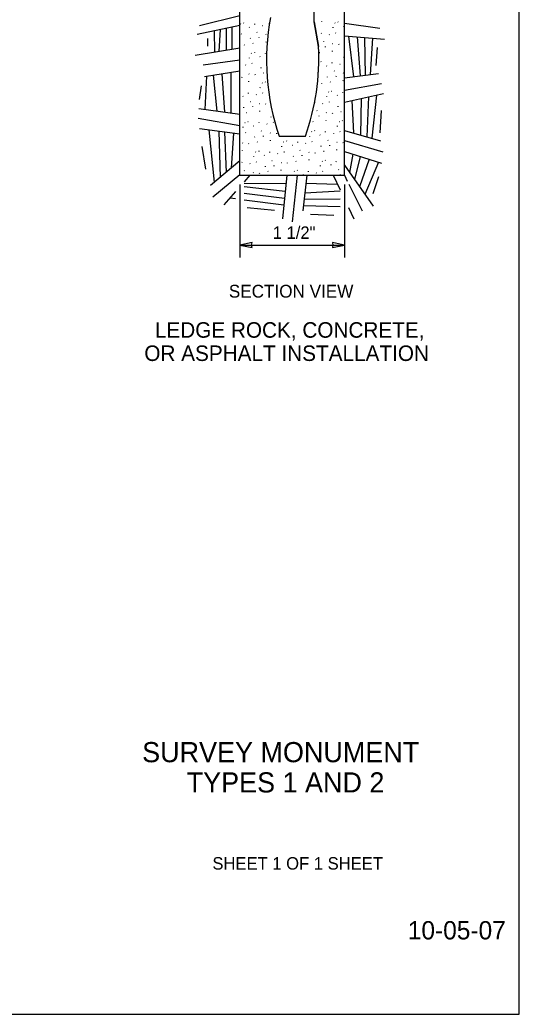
# Model space of a CAD drawing. Extents: x 99862 to 103151, y 100000 to 102076.
# Drawn here: x 102507 to 103151, y 100000 to 101282 of the extents above; entities that cross this region are included whole.
import ezdxf

# ---------------------------------------------------------------- set-up
doc = ezdxf.new("R2010")
doc.units = 0
for name, color, linetype in [('Level 1', 7, 'Continuous'), ('Level 11', 7, 'Continuous'), ('Level 15', 7, 'Continuous'), ('Level 20', 7, 'Continuous'), ('Level 21', 7, 'Continuous'), ('Level 26', 7, 'Continuous'), ('Level 28', 7, 'Continuous'), ('Level 6', 7, 'Continuous'), ('Level 62', 7, 'Continuous')]:
    doc.layers.add(name, color=color, linetype=linetype)

msp = doc.modelspace()

# ---------------------------------------------------------------- linework, layer by layer
at = {"layer": 'Level 1'}
msp.add_lwpolyline([(99862, 99999.5), (103151, 99999.5), (103151, 102075.5), (99862, 102075.5)], close=True, dxfattribs=at)
at = {"layer": 'Level 11'}
for p, q in [((102790.8, 101081.2), (102790.8, 101368.8)), ((102925.8, 101081.2), (102925.8, 101368.8)), ((102790.8, 101081.2), (102925.8, 101081.2))]:
    msp.add_line(p, q, dxfattribs=at)
at = {"layer": 'Level 15'}
for p, q in [((102790.8, 101069.2), (102790.8, 100975.2)), ((102925.8, 101069.2), (102925.8, 100975.2)), ((102790.8, 100991.2), (102925.8, 100991.2))]:
    msp.add_line(p, q, dxfattribs=at)
for points in [[(102790.8, 100991.2), (102806.5, 100988.1), (102805.8, 100991.2), (102806.5, 100994.3)], [(102925.8, 100991.2), (102910.1, 100994.3), (102910.8, 100991.2), (102910.1, 100988.1)]]:
    msp.add_lwpolyline(points, close=True, dxfattribs=at)
at = {"layer": 'Level 26'}
for p, q in [((102791.7, 101276.5), (102792.1, 101276.2)), ((102795.6, 101277.8), (102796, 101277.4)), ((102802.8, 101272.2), (102803.2, 101271.9)), ((102810.1, 101275.7), (102810.1, 101276.5)), ((102820.1, 101274.5), (102820.5, 101274.2)), ((102828.3, 101276.7), (102828.8, 101276.4)), ((102896.5, 101278.9), (102896.6, 101279.6)), ((102911.3, 101271.3), (102911.3, 101272)), ((102913.4, 101277.7), (102913.8, 101277.4)), ((102917.3, 101279), (102917.8, 101278.7)), ((102924.5, 101273.4), (102924.9, 101273.1)), ((102792.4, 101263.6), (102792.8, 101263.3)), ((102804.3, 101257.4), (102804.4, 101258.1)), ((102812.7, 101265.6), (102813.2, 101265.3)), ((102815.6, 101258.3), (102815.7, 101259)), ((102824.5, 101263.1), (102824.9, 101262.8)), ((102895.8, 101263.9), (102895.9, 101264.6)), ((102905.8, 101262.6), (102906.3, 101262.3)), ((102914.1, 101264.8), (102914.5, 101264.5)), ((102796.4, 101249.4), (102796.6, 101248.8)), ((102807.6, 101251.5), (102808, 101251.2)), ((102824.6, 101252.7), (102824.7, 101253.4)), ((102898.5, 101253.7), (102898.9, 101253.4)), ((102901.4, 101246.5), (102901.4, 101247.2)), ((102910.3, 101251.2), (102910.7, 101250.9)), ((102918.1, 101250.6), (102918.4, 101250)), ((102803.4, 101232), (102803.4, 101232.7)), ((102805.6, 101238.5), (102806, 101238.2)), ((102809.5, 101239.7), (102809.9, 101239.4)), ((102816.6, 101234.2), (102817, 101233.9)), ((102823.9, 101237.7), (102823.9, 101238.4)), ((102893.4, 101239.6), (102893.8, 101239.3)), ((102910.4, 101240.9), (102910.4, 101241.6)), ((102925.1, 101233.2), (102925.2, 101234)), ((102798, 101223.4), (102798.4, 101223.1)), ((102806.2, 101225.6), (102806.6, 101225.2)), ((102818.2, 101219.3), (102818.2, 101220)), ((102895.2, 101227.9), (102895.6, 101227.6)), ((102902.4, 101222.3), (102902.8, 101222)), ((102909.7, 101225.9), (102909.7, 101226.6)), ((102919.7, 101224.6), (102920.1, 101224.3)), ((102790.8, 101214.3), (102791, 101214.1)), ((102793.5, 101207.2), (102793.6, 101207.9)), ((102802.4, 101211.9), (102802.8, 101211.6)), ((102810.2, 101211.4), (102810.5, 101210.8)), ((102821.5, 101213.4), (102821.9, 101213.1)), ((102892, 101213.7), (102892.4, 101213.4)), ((102903.9, 101207.5), (102904, 101208.2)), ((102912.3, 101215.7), (102912.8, 101215.4)), ((102915.2, 101208.4), (102915.3, 101209.2)), ((102924.1, 101213.2), (102924.5, 101212.9)), ((102924.2, 101202.8), (102924.3, 101203.6)), ((102802.5, 101201.6), (102802.6, 101202.3)), ((102817.2, 101194), (102817.3, 101194.7)), ((102819.4, 101200.4), (102819.8, 101200.1)), ((102823.3, 101201.7), (102823.7, 101201.4)), ((102896, 101199.5), (102896.2, 101198.9)), ((102907.2, 101201.6), (102907.6, 101201.3)), ((102794.5, 101183.1), (102794.9, 101182.7)), ((102801.8, 101186.6), (102801.8, 101187.3)), ((102811.8, 101185.3), (102812.2, 101185)), ((102820.1, 101187.5), (102820.5, 101187.2)), ((102903, 101182.1), (102903, 101182.8)), ((102905.2, 101188.6), (102905.6, 101188.3)), ((102909.1, 101189.8), (102909.5, 101189.5)), ((102916.2, 101184.3), (102916.6, 101184)), ((102923.5, 101187.8), (102923.5, 101188.5)), ((102796.1, 101168.2), (102796.1, 101168.9)), ((102804.5, 101176.4), (102804.9, 101176.1)), ((102807.4, 101169.2), (102807.4, 101169.9)), ((102816.3, 101173.9), (102816.7, 101173.6)), ((102824, 101173.3), (102824.3, 101172.8)), ((102887.5, 101174.7), (102887.6, 101175.5)), ((102897.6, 101173.5), (102898, 101173.2)), ((102905.8, 101175.7), (102906.2, 101175.4)), ((102917.8, 101169.4), (102917.8, 101170.2)), ((102799.3, 101162.3), (102799.8, 101162)), ((102816.4, 101163.6), (102816.4, 101164.3)), ((102831.1, 101156), (102831.1, 101156.7)), ((102890.2, 101164.6), (102890.6, 101164.3)), ((102893.1, 101157.3), (102893.2, 101158)), ((102902, 101162.1), (102902.4, 101161.7)), ((102902.1, 101151.7), (102902.2, 101152.4)), ((102909.8, 101161.5), (102910.1, 101160.9)), ((102921, 101163.5), (102921.5, 101163.2)), ((102795.1, 101142.9), (102795.2, 101143.6)), ((102797.3, 101149.3), (102797.7, 101149)), ((102801.2, 101150.6), (102801.6, 101150.3)), ((102808.3, 101145), (102808.8, 101144.7)), ((102815.6, 101148.6), (102815.7, 101149.3)), ((102825.6, 101147.3), (102826.1, 101147)), ((102833.9, 101149.5), (102834.3, 101149.2)), ((102885.1, 101150.5), (102885.5, 101150.2)), ((102916.8, 101144.1), (102916.9, 101144.8)), ((102919, 101150.6), (102919.4, 101150.3)), ((102922.9, 101151.8), (102923.3, 101151.5)), ((102797.9, 101136.4), (102798.4, 101136.1)), ((102809.9, 101130.2), (102810, 101130.9)), ((102818.3, 101138.4), (102818.7, 101138.1)), ((102821.2, 101131.2), (102821.2, 101131.9)), ((102830.1, 101135.9), (102830.5, 101135.6)), ((102837.9, 101135.3), (102838.2, 101134.7)), ((102880.9, 101131), (102880.9, 101131.7)), ((102883, 101137.5), (102883.5, 101137.2)), ((102886.9, 101138.7), (102887.4, 101138.4)), ((102894.1, 101133.2), (102894.5, 101132.9)), ((102901.4, 101136.7), (102901.4, 101137.4)), ((102911.4, 101135.5), (102911.8, 101135.2)), ((102919.7, 101137.6), (102920.1, 101137.3)), ((102794.1, 101122.8), (102794.6, 101122.5)), ((102801.9, 101122.2), (102802.2, 101121.6)), ((102813.2, 101124.3), (102813.6, 101124)), ((102830.2, 101125.6), (102830.3, 101126.3)), ((102844.9, 101117.9), (102845, 101118.6)), ((102847.1, 101124.4), (102847.5, 101124.1)), ((102851, 101125.6), (102851.4, 101125.3)), ((102858.1, 101120.1), (102858.6, 101119.8)), ((102865.4, 101123.6), (102865.5, 101124.3)), ((102875.4, 101122.4), (102875.9, 101122.1)), ((102883.7, 101124.6), (102884.1, 101124.2)), ((102895.7, 101118.3), (102895.7, 101119)), ((102904.1, 101126.5), (102904.5, 101126.2)), ((102907, 101119.3), (102907, 101120)), ((102915.9, 101124), (102916.3, 101123.7)), ((102916, 101113.7), (102916, 101114.4)), ((102923.6, 101123.5), (102923.9, 101122.9)), ((102794.2, 101112.5), (102794.3, 101113.2)), ((102809, 101104.8), (102809, 101105.5)), ((102811.1, 101111.3), (102811.5, 101111)), ((102815, 101112.5), (102815.5, 101112.2)), ((102822.2, 101107), (102822.6, 101106.7)), ((102829.5, 101110.5), (102829.5, 101111.2)), ((102839.5, 101109.3), (102839.9, 101109)), ((102847.7, 101111.5), (102848.2, 101111.2)), ((102859.7, 101105.2), (102859.8, 101106)), ((102868.1, 101113.4), (102868.5, 101113.1)), ((102871, 101106.2), (102871, 101106.9)), ((102879.9, 101110.9), (102880.3, 101110.6)), ((102880, 101100.6), (102880.1, 101101.3)), ((102887.7, 101110.4), (102888, 101109.8)), ((102898.9, 101112.4), (102899.4, 101112.1)), ((102793.5, 101097.5), (102793.6, 101098.2)), ((102803.5, 101096.2), (102804, 101095.9)), ((102811.8, 101098.4), (102812.2, 101098.1)), ((102823.8, 101092.2), (102823.8, 101092.9)), ((102832.2, 101100.4), (102832.6, 101100)), ((102835, 101093.1), (102835.1, 101093.8)), ((102843.9, 101097.8), (102844.4, 101097.5)), ((102844, 101087.5), (102844.1, 101088.2)), ((102851.7, 101097.3), (102852, 101096.7)), ((102863, 101099.3), (102863.4, 101099)), ((102894.7, 101093), (102894.8, 101093.7)), ((102896.9, 101099.4), (102897.3, 101099.1)), ((102900.8, 101100.7), (102901.2, 101100.4)), ((102907.9, 101095.1), (102908.4, 101094.8)), ((102915.2, 101098.7), (102915.3, 101099.4)), ((102917.9, 101088.5), (102918.3, 101088.2)), ((102925.2, 101097.4), (102925.7, 101097.1)), ((102796.2, 101087.3), (102796.6, 101087)), ((102808, 101084.8), (102808.4, 101084.5)), ((102815.8, 101084.2), (102816.1, 101083.6)), ((102827, 101086.3), (102827.4, 101085.9)), ((102860.9, 101086.4), (102861.3, 101086)), ((102864.8, 101087.6), (102865.3, 101087.3)), ((102872, 101082.1), (102872.4, 101081.7)), ((102879.3, 101085.6), (102879.3, 101086.3)), ((102889.3, 101084.3), (102889.7, 101084)), ((102897.5, 101086.5), (102898, 101086.2)), ((102920.8, 101081.3), (102920.8, 101082))]:
    msp.add_line(p, q, dxfattribs=at)
at = {"layer": 'Level 28'}
for p, q in [((102790.8, 101286.7), (102738.8, 101273.9)), ((102790.8, 101274.4), (102735.6, 101262.9)), ((102765.3, 101269.1), (102763.8, 101240.6)), ((102773.3, 101270.8), (102773.3, 101242.1)), ((102780.3, 101272.2), (102780.3, 101243.3)), ((102925.8, 101277.3), (102971.2, 101270.8)), ((102748.9, 101257.5), (102748.9, 101247.8)), ((102757.6, 101267.5), (102758.3, 101239.7)), ((102925.8, 101261.1), (102977.4, 101256.7)), ((102930.9, 101260.7), (102937.3, 101208.1)), ((102942.3, 101259.7), (102946.1, 101209.2)), ((102951.7, 101258.9), (102952.5, 101210)), ((102962, 101258), (102959, 101210.9)), ((102790.8, 101245), (102733.3, 101235.6)), ((102967.7, 101246.1), (102966.4, 101222.7)), ((102790.8, 101229.7), (102743.4, 101223.2)), ((102790.8, 101215.4), (102745, 101208.3)), ((102747.7, 101208.8), (102745.5, 101165.9)), ((102756.2, 101210.1), (102761.3, 101163.7)), ((102767.5, 101211.8), (102771.1, 101162.4)), ((102779.4, 101161.2), (102779.4, 101213.6)), ((102925.8, 101206.6), (102969.6, 101212.2)), ((102741, 101196.7), (102738.3, 101179)), ((102925.8, 101191.1), (102973.5, 101199.7)), ((102925.8, 101175.6), (102975.9, 101186.5)), ((102947.2, 101180.2), (102946.5, 101133)), ((102956.8, 101182.3), (102954.7, 101130.6)), ((102967, 101184.5), (102961, 101128.8)), ((102790.8, 101159.6), (102738, 101167)), ((102935.2, 101177.6), (102937.3, 101135.7)), ((102790.8, 101144.8), (102737.2, 101154.5)), ((102973, 101164.9), (102971.2, 101135.8)), ((102790.8, 101134.3), (102738.8, 101141.2)), ((102750.7, 101139.6), (102757.8, 101072.1)), ((102763.7, 101137.9), (102765.2, 101078.2)), ((102770.9, 101137), (102773, 101084.8)), ((102782.7, 101135.4), (102779.7, 101090.3)), ((102925.8, 101139), (102972, 101125.6)), ((102741.9, 101118.1), (102746.3, 101089)), ((102925.8, 101126.1), (102975.1, 101111.6)), ((102925.8, 101111.7), (102973.5, 101096.8)), ((102936.4, 101108.4), (102932.4, 101084.7)), ((102946, 101105.4), (102938.7, 101075.6)), ((102957.5, 101101.8), (102945.2, 101066.4)), ((102790.8, 101099.6), (102752.8, 101067.9)), ((102925.8, 101094.1), (102962.6, 101041.4)), ((102969.7, 101098), (102952.2, 101056.3)), ((102790.8, 101081.7), (102755.9, 101053.1)), ((102803.7, 101081.2), (102796.3, 101072.8)), ((102851.4, 101081.2), (102845.6, 101025)), ((102864.9, 101081.2), (102858.1, 101021.1)), ((102877.2, 101081.2), (102872.1, 101035.1)), ((102911.3, 101081.2), (102920.2, 101062.2)), ((102925.6, 101081.2), (102929.3, 101073.6)), ((102969.5, 101079.3), (102962.4, 101057.2)), ((102796.3, 101071.1), (102850.3, 101070.4)), ((102796.3, 101066.6), (102849.3, 101060.6)), ((102876.1, 101071.1), (102916.7, 101069.7)), ((102931.3, 101069.7), (102948.6, 101035.1)), ((102785.2, 101060.2), (102770, 101042.9)), ((102778.1, 101052.1), (102785.2, 101051.2)), ((102784.5, 101059.4), (102785.2, 101059.3)), ((102796.3, 101057.9), (102848.4, 101051.7)), ((102796.3, 101049.7), (102847.5, 101043.1)), ((102873.8, 101050.3), (102920.2, 101050.9)), ((102874.7, 101058.4), (102920.2, 101061.2)), ((102800.1, 101039.6), (102835.4, 101036.1)), ((102872.9, 101042.3), (102920.2, 101041)), ((102930.8, 101039.6), (102937.7, 101025)), ((102882.1, 101030.8), (102912.1, 101029.9))]:
    msp.add_line(p, q, dxfattribs=at)
at = {"layer": 'Level 6'}
for p, q in [((102886.5, 101279.1), (102886.5, 101294.9)), ((102886.5, 101279.1), (102886.5, 101294.9)), ((102886.5, 101279.1), (102892.1, 101247.3)), ((102892.1, 101247.3), (102886.5, 101279.1)), ((102841.5, 101131.5), (102841.4, 101131.4)), ((102841.4, 101131.4), (102875.3, 101131.4)), ((102841.4, 101131.4), (102875.2, 101131.4))]:
    msp.add_line(p, q, dxfattribs=at)
for centre, radius, start, end in [((103129.9, 101229.7), 304.7, 169.5778, 198.8057), ((103129.9, 101229.7), 304.7, 169.5778, 198.8057), ((102595.3, 101231.4), 297.3, 340.3543, 3.0662), ((102595.3, 101231.4), 297.3, 340.3543, 3.06)]:
    msp.add_arc(centre, radius, start, end, dxfattribs=at)

# ---------------------------------------------------------------- texts
at = {"layer": 'Level 20'}
for s, height, p in [('1 1/2"', 16, (102833.2, 100999.2)), ('10-05-07', 23.62, (103007.4, 100095.8))]:
    msp.add_text(s, height=height, dxfattribs=at).set_placement(p)
at = {"layer": 'Level 21'}
for s, height, p in [('SECTION VIEW', 16.5, (102776.6, 100923.4)), ('LEDGE ROCK, CONCRETE,', 20, (102681.2, 100871.7)), ('OR ASPHALT INSTALLATION', 20, (102667.6, 100841.7))]:
    msp.add_text(s, height=height, dxfattribs=at).set_placement(p)
at = {"layer": 'Level 62'}
for s, height, p in [('SURVEY MONUMENT', 26, (102664.8, 100324.3)), ('TYPES 1 AND 2', 26, (102722.2, 100285.3)), ('SHEET 1 OF 1 SHEET', 16, (102755.4, 100185.9))]:
    msp.add_text(s, height=height, dxfattribs=at).set_placement(p)

doc.saveas('drawing.dxf')
